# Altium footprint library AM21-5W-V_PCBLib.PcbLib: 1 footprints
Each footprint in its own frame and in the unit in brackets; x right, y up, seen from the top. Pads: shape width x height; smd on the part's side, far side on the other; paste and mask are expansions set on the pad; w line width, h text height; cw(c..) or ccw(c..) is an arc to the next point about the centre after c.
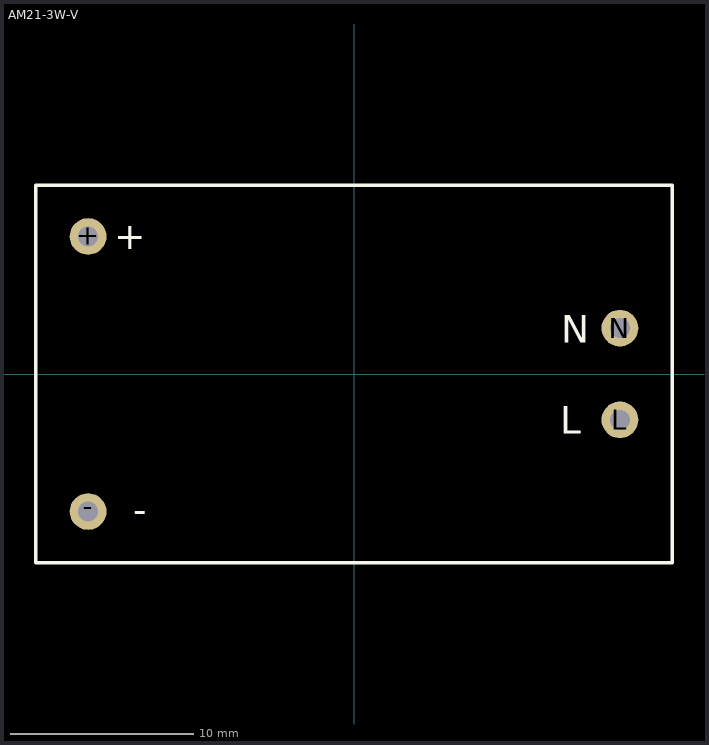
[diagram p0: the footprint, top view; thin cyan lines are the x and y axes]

## AM21-3W-V [mm]
pads (4):
  round 2 hole 1.1: +(-14.5,7.5) -(-14.5,-7.5) L(14.5,-2.5) N(14.5,2.5)
TopOverlay:
  lines w0.2: -17.35,-10.3 -17.35,10.3 17.35,10.3 17.35,-10.3 -17.35,-10.3
  text "+" at -11.35,6.8 h1.5
  text "-" at -11.3,-8.15 h1.5
  text "L" at 11.25,-3.25 h1.5
  text "N" at 11.3,1.7 h1.5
